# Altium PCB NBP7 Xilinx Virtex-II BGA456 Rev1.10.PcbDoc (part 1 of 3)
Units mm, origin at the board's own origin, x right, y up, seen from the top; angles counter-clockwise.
Board outline 69 x 80.99 mm, 6 copper layers (Top Layer, MidLayer1, InternalPlane1, InternalPlane2, MidLayer2, Bottom Layer); 101 components, 273 nets, 963 pads, 545 vias.
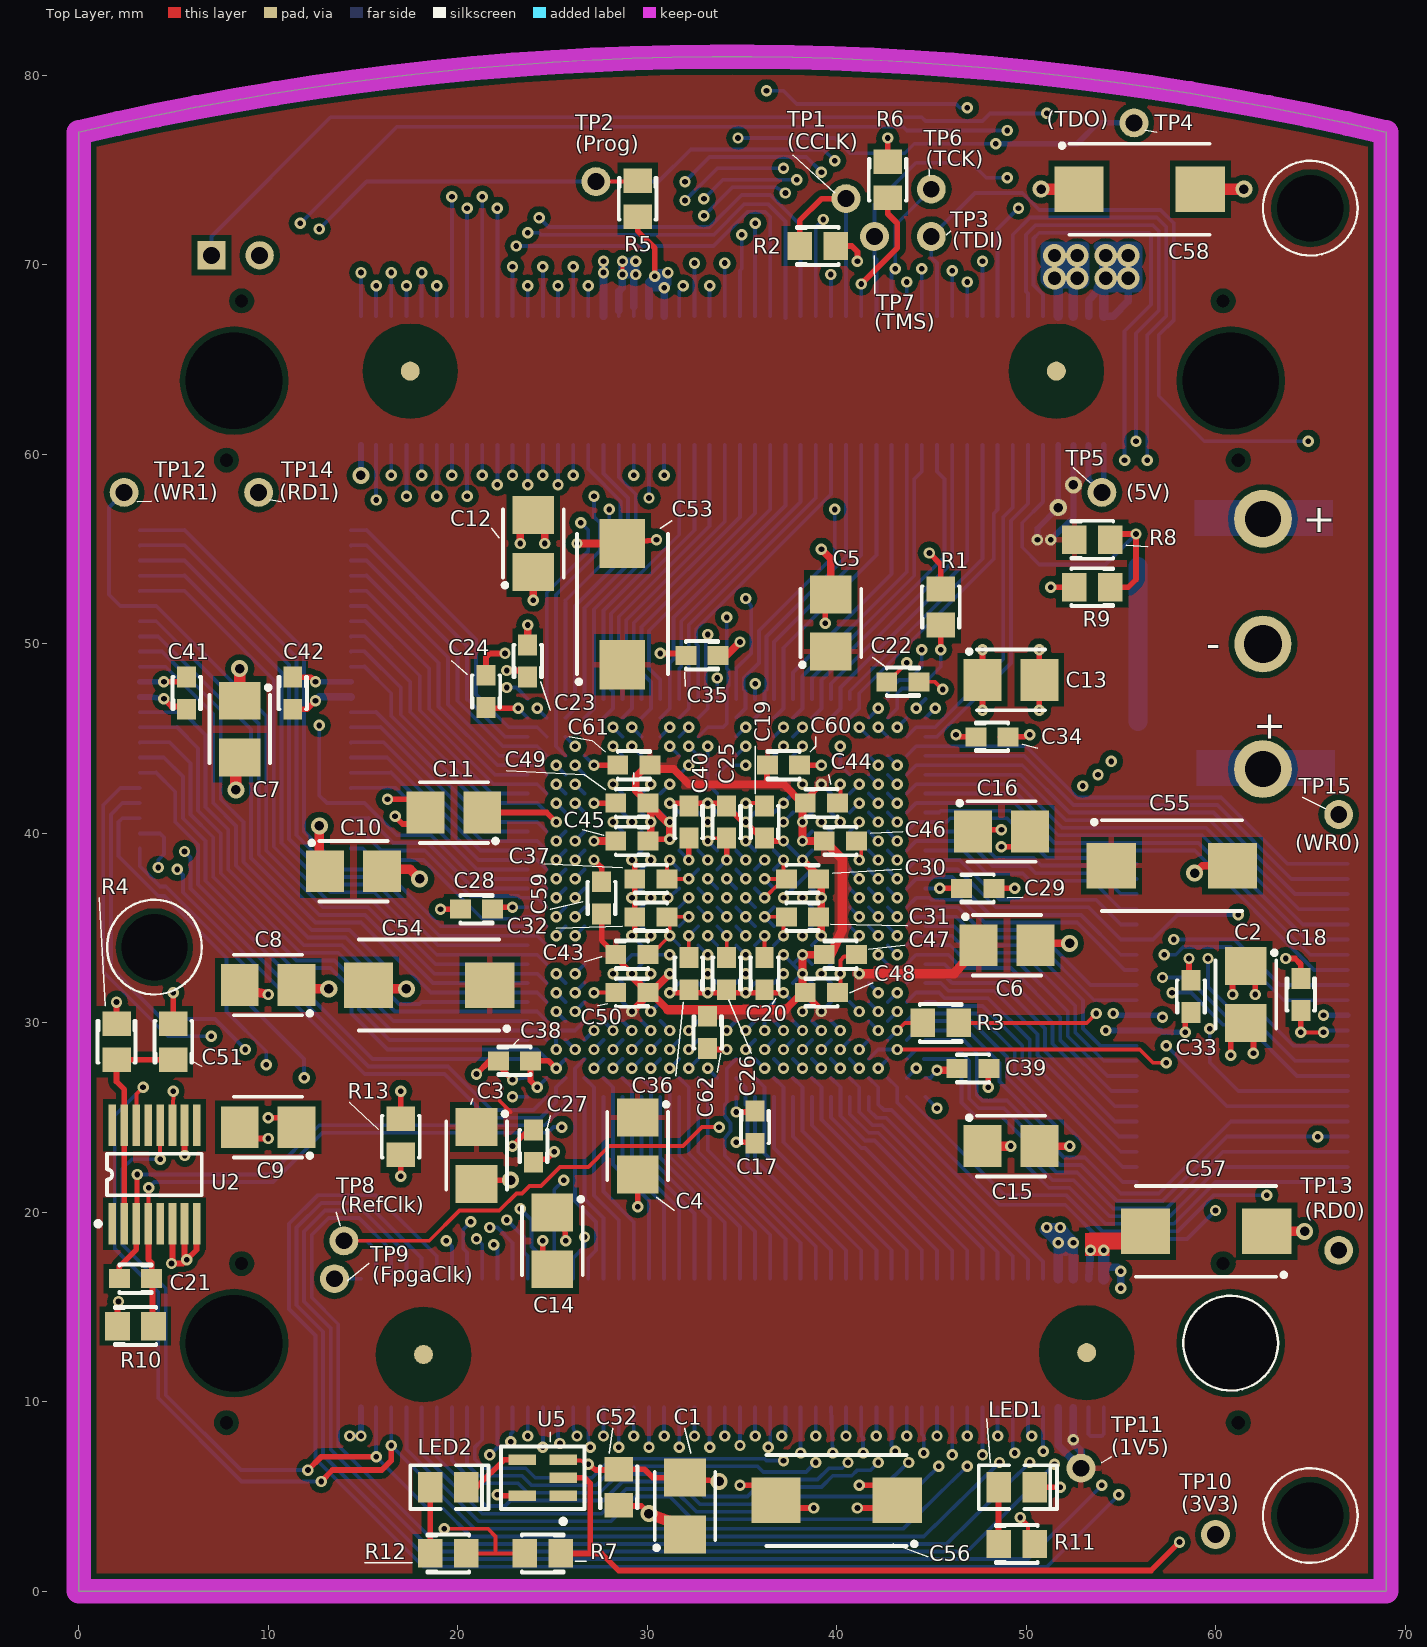
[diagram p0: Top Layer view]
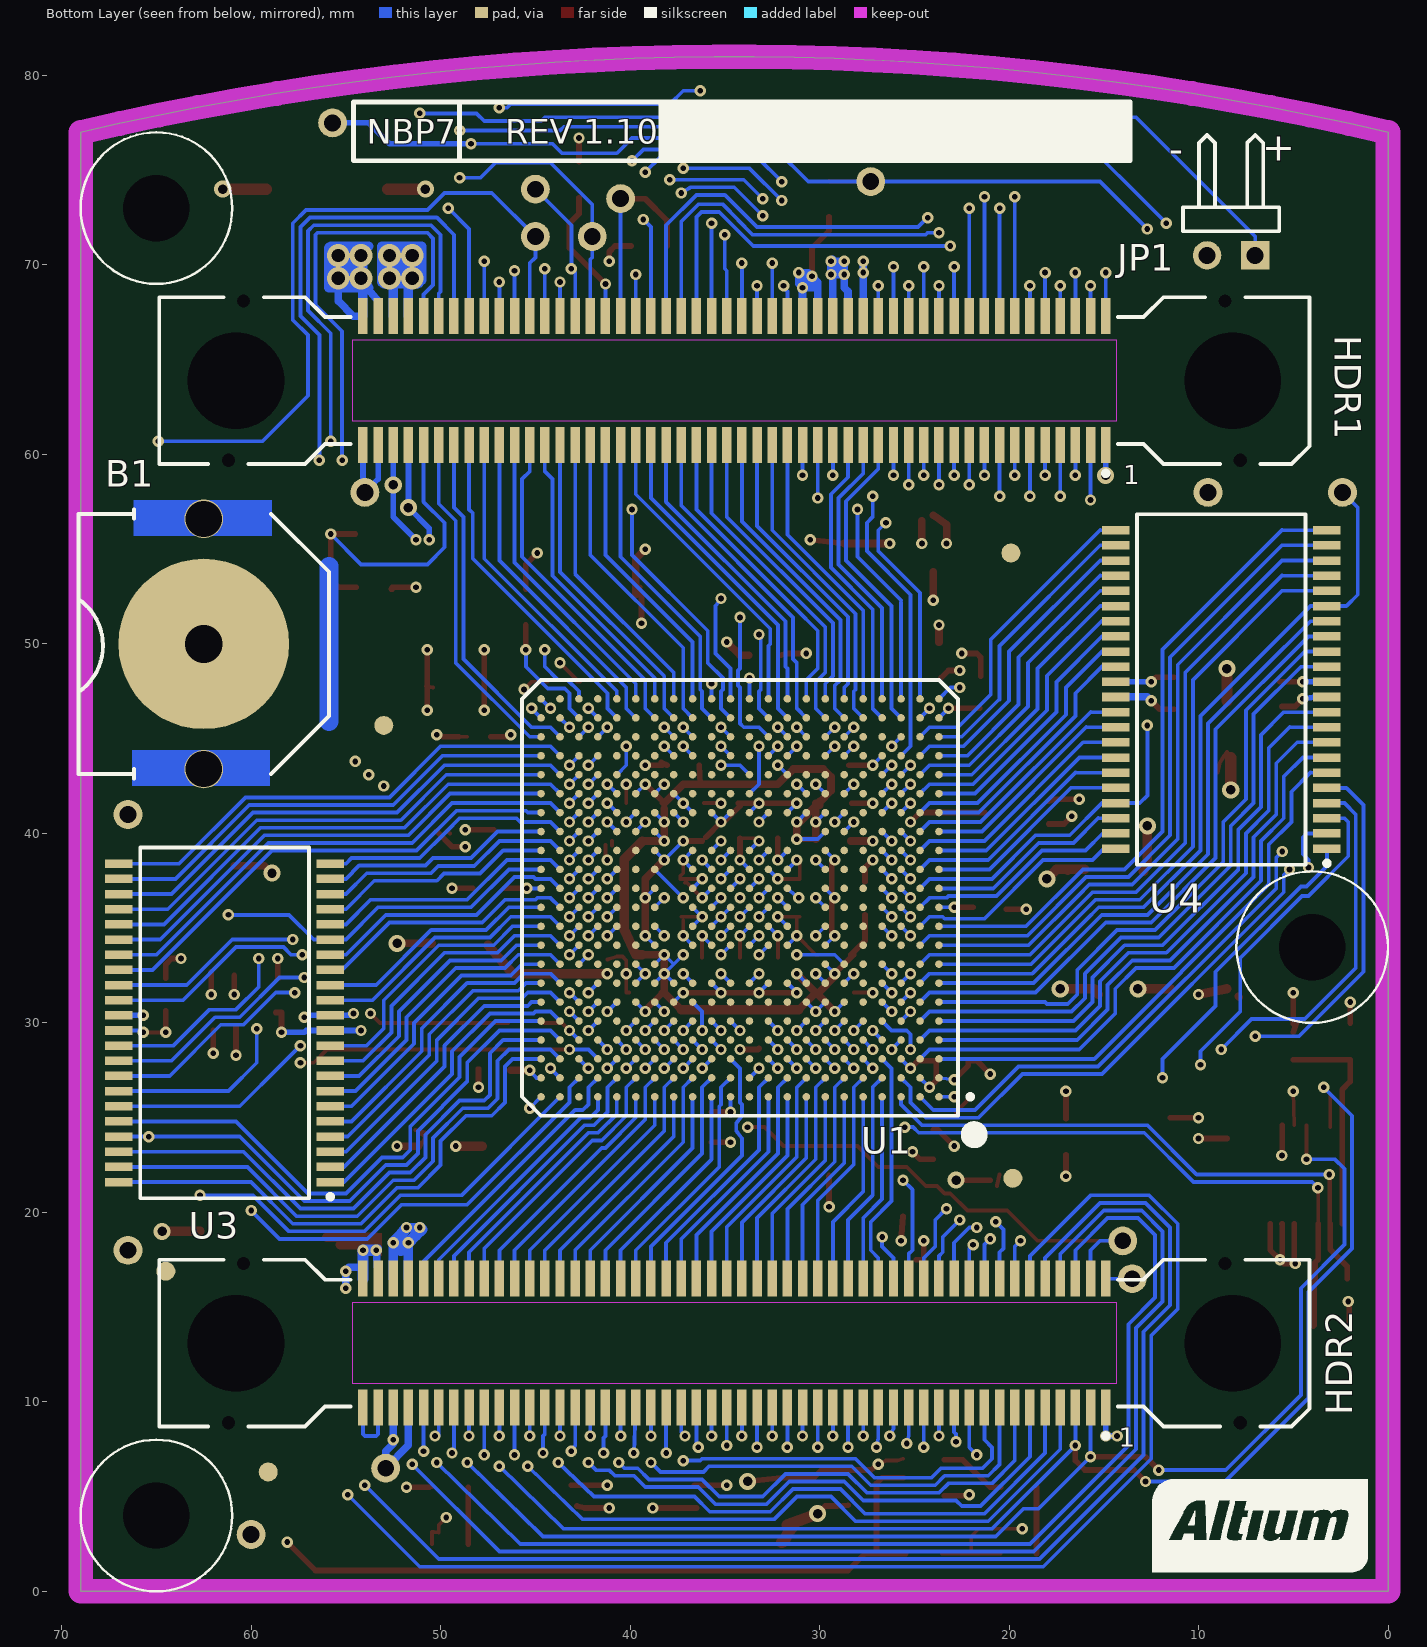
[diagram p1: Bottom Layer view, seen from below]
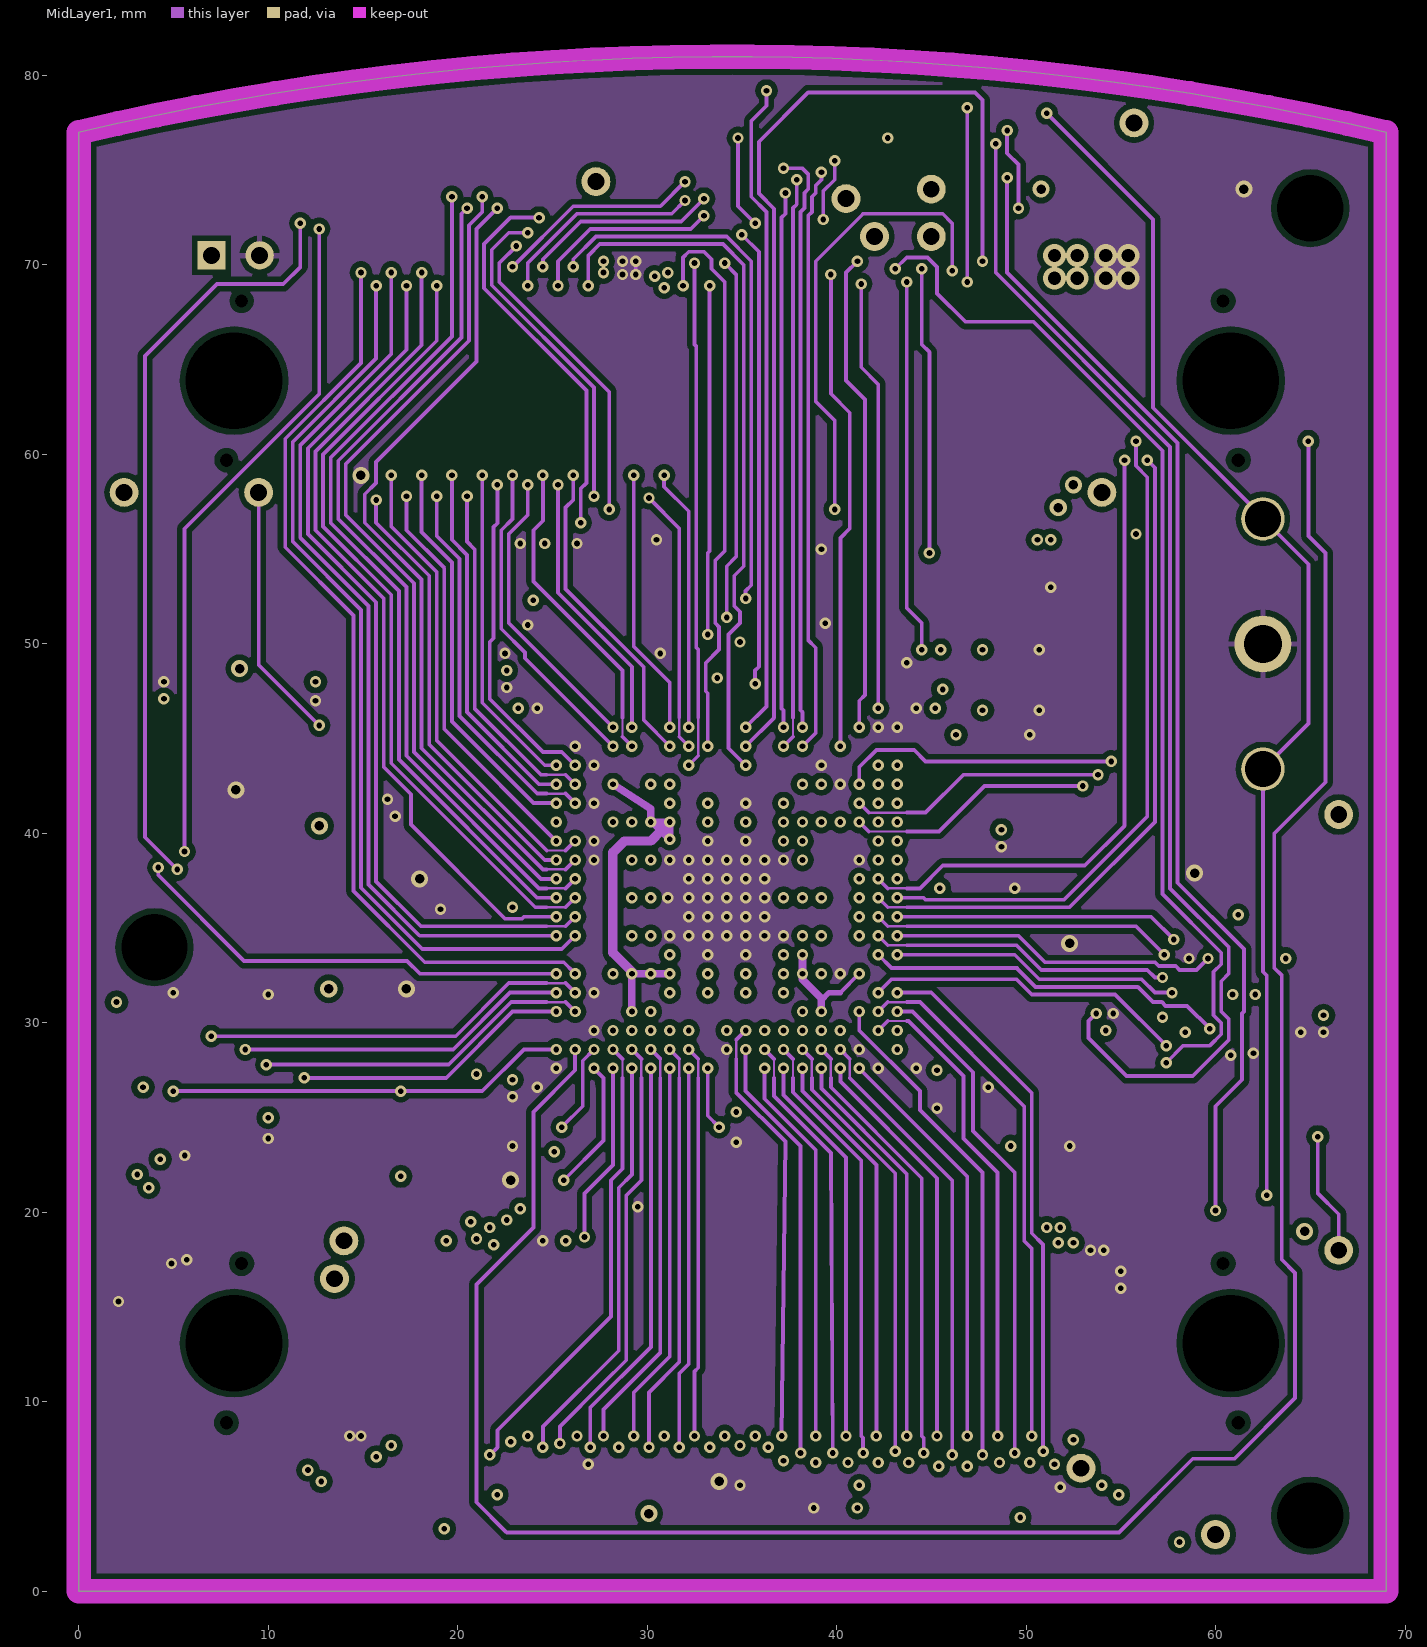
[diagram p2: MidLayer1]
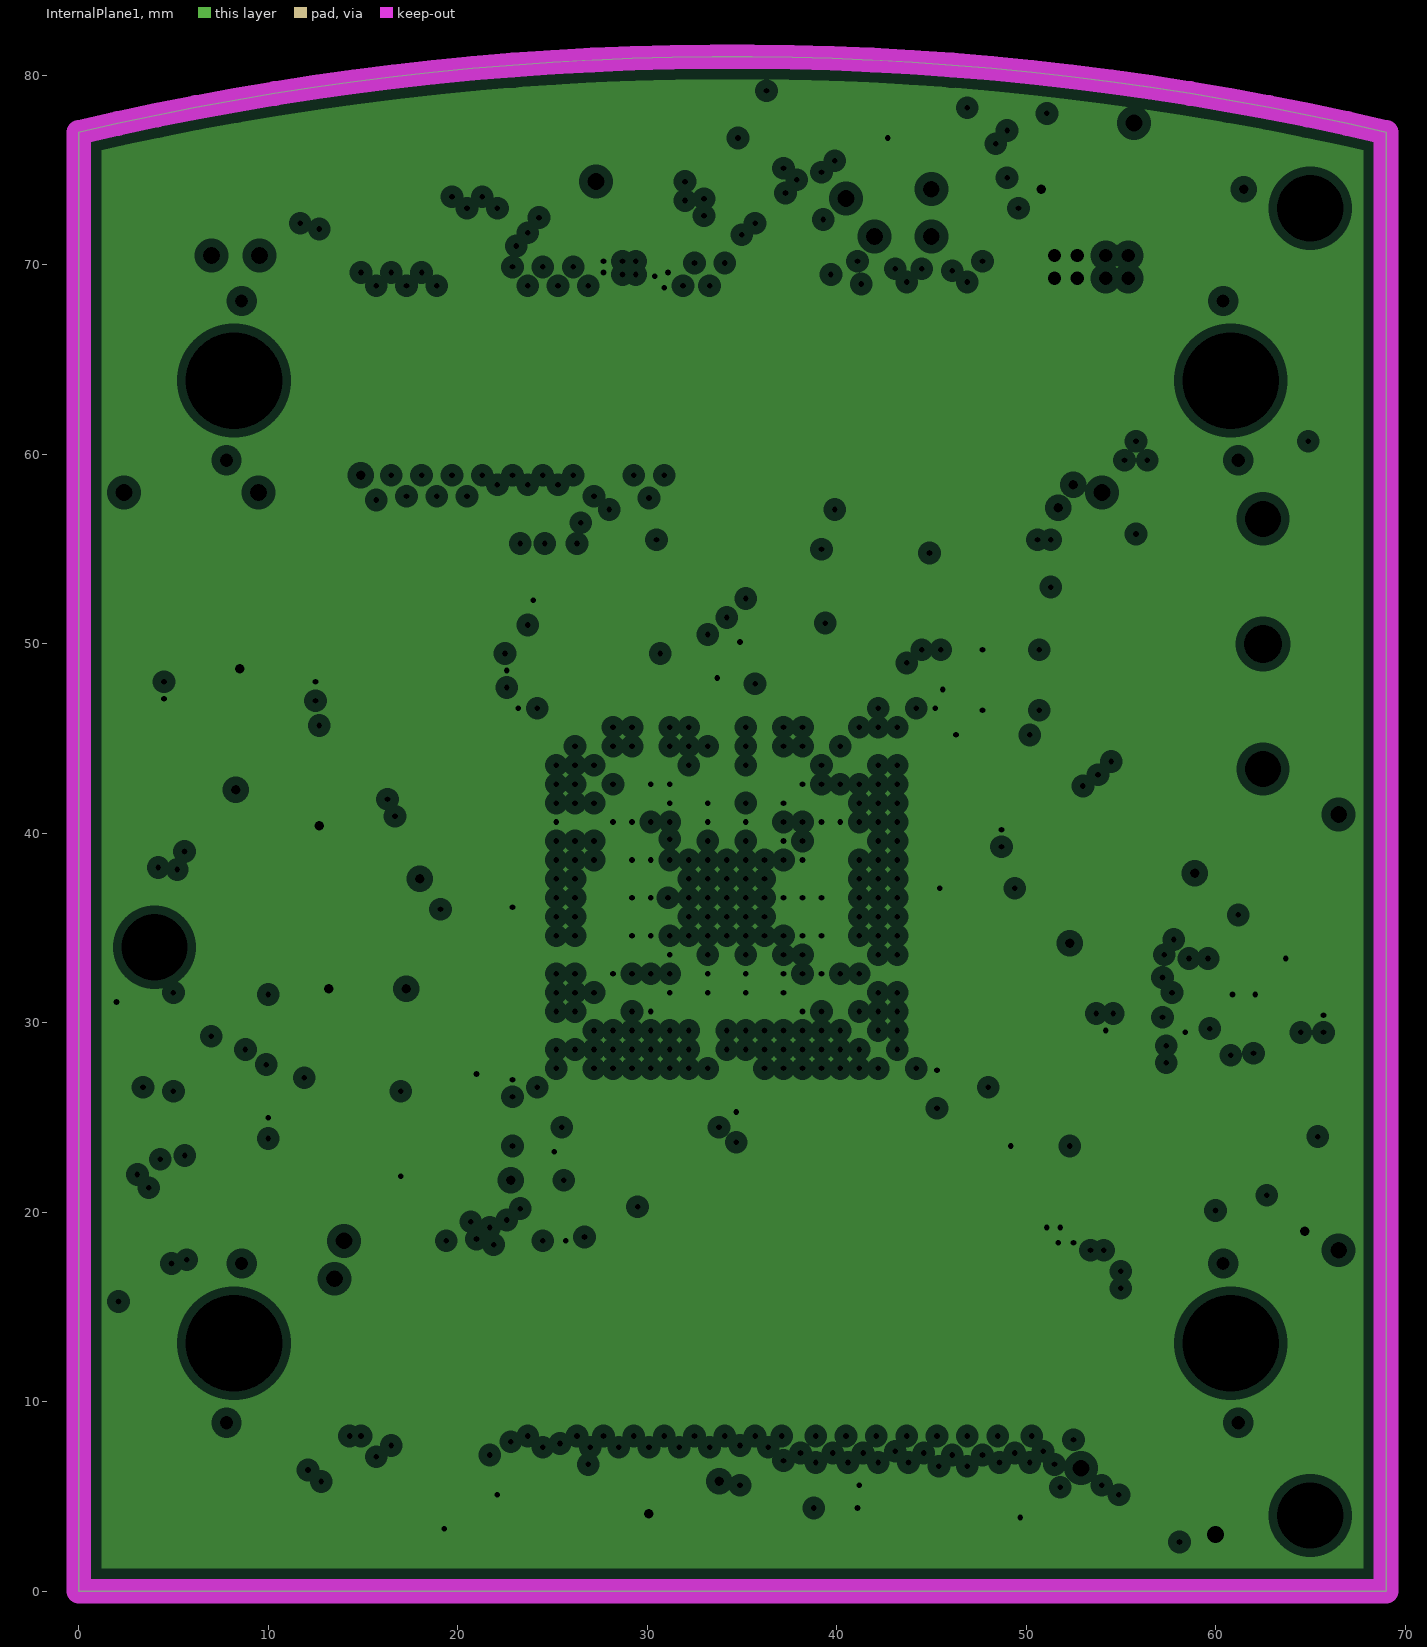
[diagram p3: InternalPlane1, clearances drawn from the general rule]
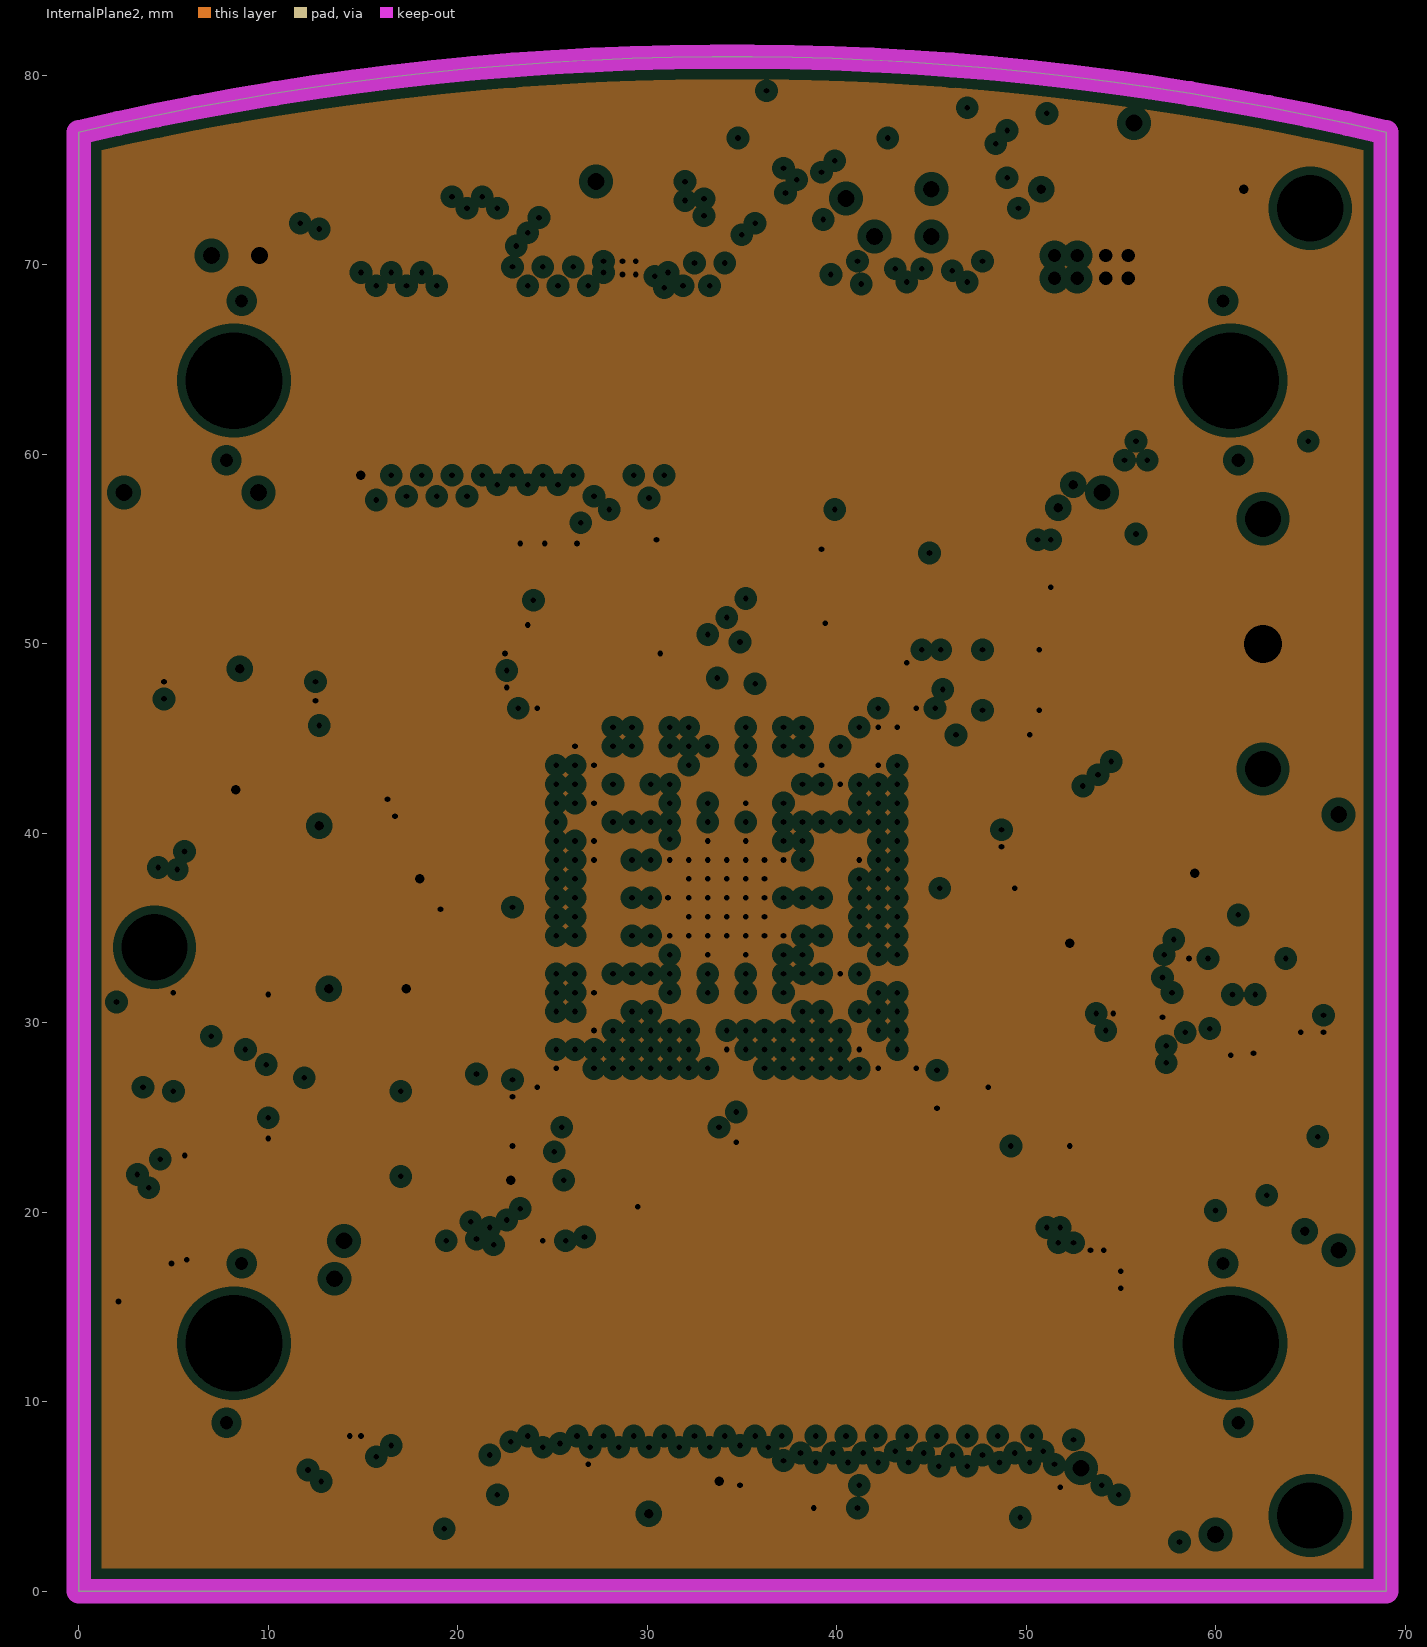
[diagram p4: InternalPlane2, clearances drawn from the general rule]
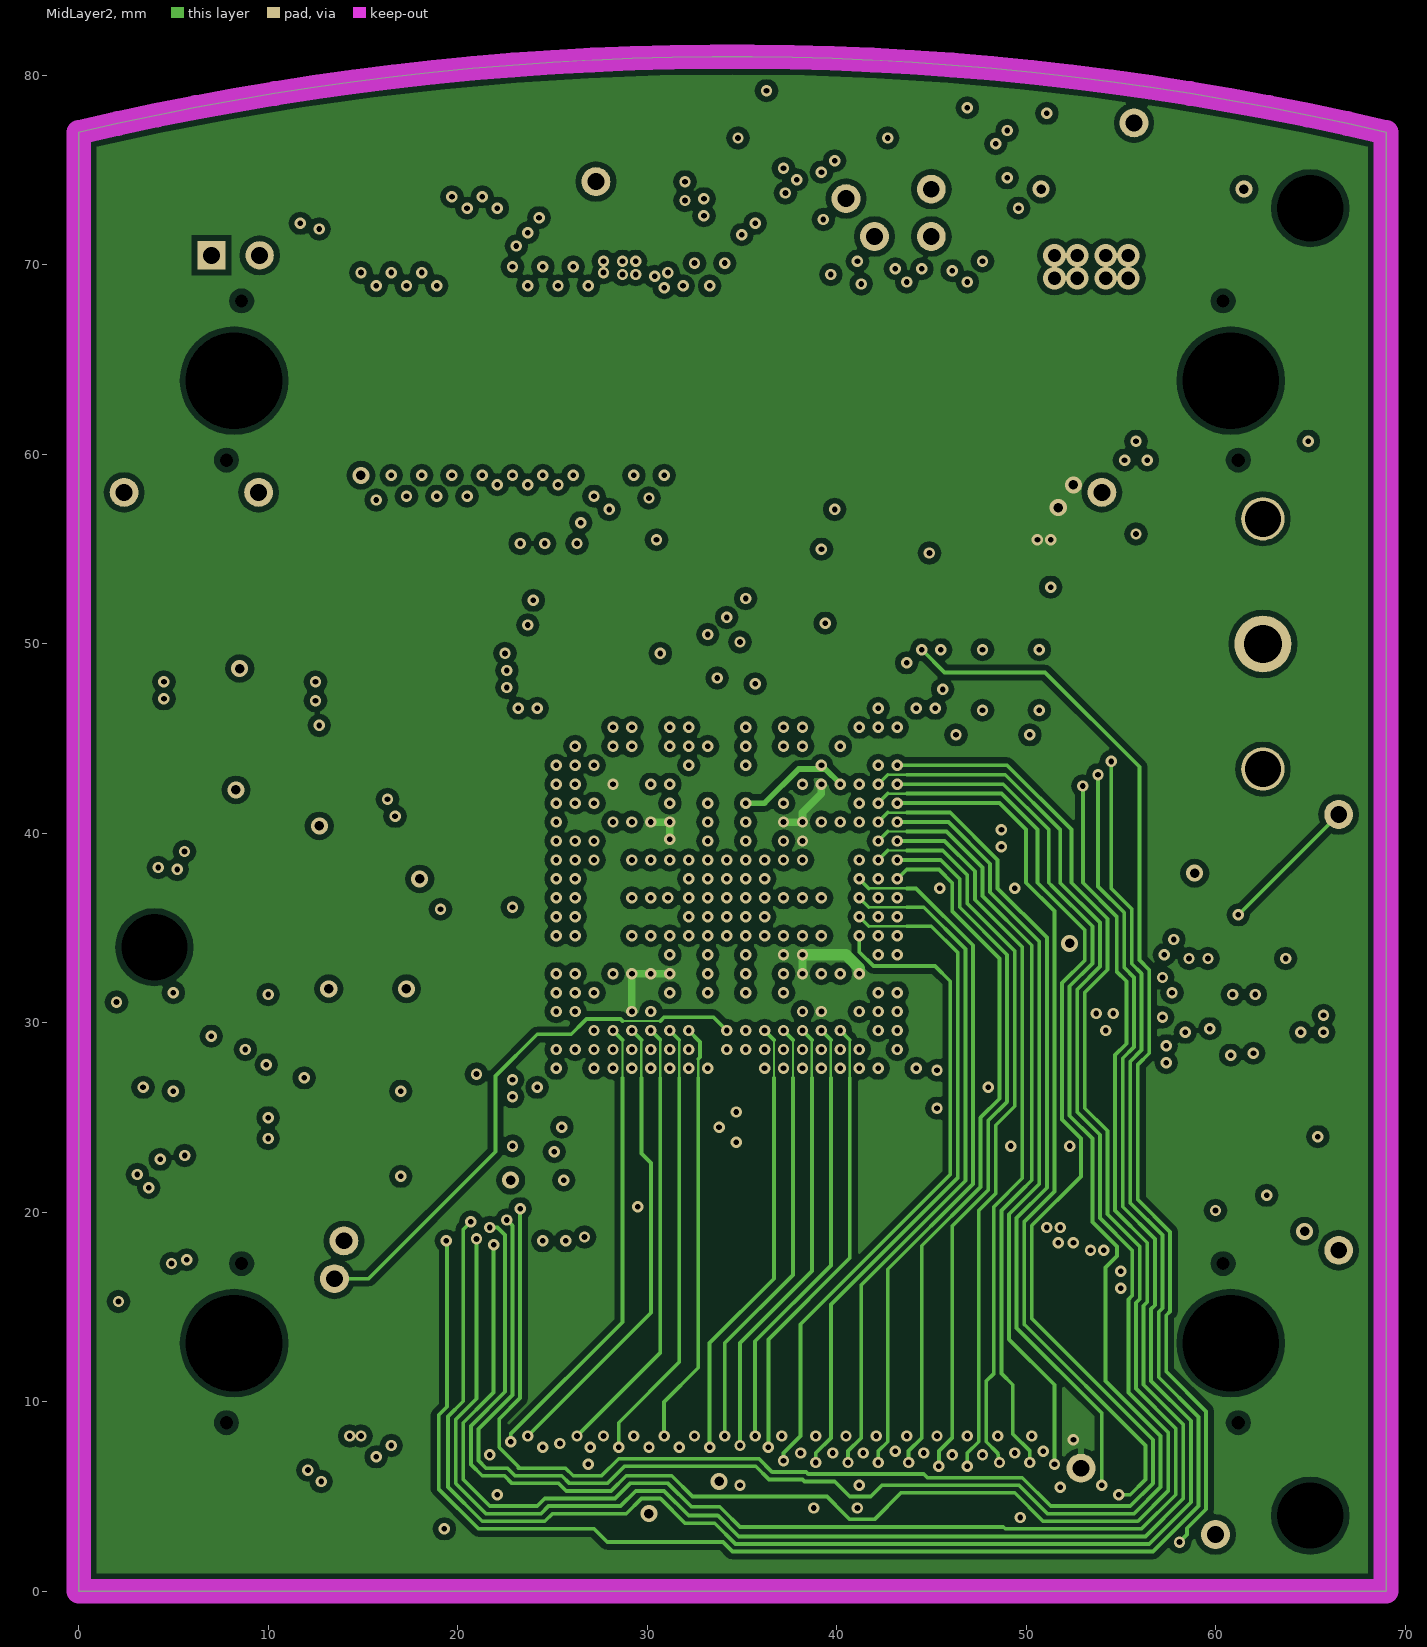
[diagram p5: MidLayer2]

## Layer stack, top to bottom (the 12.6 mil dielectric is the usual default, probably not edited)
Top Layer: signal copper 0.0356
Dielectric: core 0.32, FR-4, Dk 4.8
MidLayer1: signal copper 0.0356
Dielectric: prepreg 0.32, FR-4, Dk 4.8
InternalPlane1: plane copper 0.0356, net VCC
Dielectric: core 0.32, FR-4, Dk 4.8
InternalPlane2: plane copper 0.0356, net GND
Dielectric: prepreg 0.32, FR-4, Dk 4.8
MidLayer2: signal copper 0.0356
Dielectric: core 0.32, FR-4, Dk 4.8
Bottom Layer: signal copper 0.0356

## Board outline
0,0 0.001,77 cw(c34.5,-69.801) 69,77 69,0

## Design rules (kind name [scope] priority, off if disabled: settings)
Clearance "Fiducial Clearance" [InPadClass('Fiducials')] p1: gap=2
Clearance Clearance_Polygons [InPolygon] p2: gap=0.3
Clearance "Via Pad Same Net" [IsVia vs IsPad] p3: gap=0.2
Clearance "Via-Via Clearance" [IsVia vs IsVia] p4: gap=0.3
Clearance "Mid Layer Track - Via Clearance" [(OnMid  And IsTrack) vs IsVia] p5: gap=0.127
Clearance "Bottom Layer General Clearance" [All vs OnLayer('Bottom Layer')] p6: gap=0.2
Clearance "Top Layer General Clearance" [All vs OnLayer('Top Layer')] p7: gap=0.2
Clearance "Clearance Top Layer Pads" [(OnLayer('Top Layer')) vs (InPadClass('All Pads'))] p8: gap=0.254
Clearance "General Clearance" [All] p9: gap=0.2
ComponentClearance [All] p1: gap=0.2 collisioncheckmode=3 verticalgap=0.254 showdistances=FALSE
FabricationTestPointUsage TestPointUsage [All] p1 off: valid=0 allowmultiple=FALSE
FabricationTestpoint Testpoint [All] p1 off: side=3 testpointundercomponent=TRUE minsize=1.016 maxsize=2.54 preferedsize=1.524 minholesize=0 maxholesize=1.016 preferedholesize=0.813 testpointgrid=0.025 allowsidetop=TRUE allowsidebottom=TRUE usegrid=TRUE gridtolerance=0
HoleSize [All] p1: absolutevalues=TRUE maxlimit=10 minlimit=0.3 maxpercent=80.000 minpercent=20.000
PlaneClearance [All] p1: clearance=0.45
PlaneConnect [All] p1: planeconnectstyle=Direct reliefexpansion=0.5 reliefentries=4 reliefconductorwidth=0.25 reliefairgap=0.25
PolygonConnect [All] p1: connectstyle=Relief reliefconductorwidth=0.3 reliefentries=4 polygonreliefangle="90 Angle"
RoutingVias [All] p1: holewidth=0.3 width=0.6 viastyle="Through Hole" minholewidth=0.3 minwidth=0.5 maxholewidth=0.5 maxwidth=1
SMDNeckDown [All] p1: percent=100.000
SilkscreenOverComponentPads [All] p1: minsilkscreentomaskgap=0.254
SolderMaskExpansion SolderMaskExpansion_Vias [IsVia] p1: expansion=-0.65
SolderMaskExpansion [All] p2: expansion=0.25
Width [All] p1: maxlimit=1.5 minlimit=0.127 preferedwidth=0.2 toplayer_minwidth=0.2 toplayer_prefwidth=0.203 bottomlayer_minwidth=0.2
21 further rules are at their usual default settings.

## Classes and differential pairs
pad class Fiducials: Free-4 Free-5 Free-6 Free-7
pad class PAR_DATA: U1-AA3 U1-AA4 U1-AA18 U1-AB4 U1-R18 U1-V17 U1-W5 U1-W18 U1-Y4 U1-Y5
pad class IO_CLK: U1-AB12 U1-B11 U1-E12 U1-V11
pad class IO: U1-A4 U1-A5 U1-A6 U1-A10 U1-A13 U1-A17 U1-A18 U1-A19 U1-AA5 U1-AA10 U1-AA13 U1-AA17 U1-AA18 U1-AA20 U1-AB5 U1-AB10 U1-AB13 U1-AB17 U1-AB18 U1-B4 U1-B5 U1-B6 U1-B10 U1-B12 U1-B13 U1-B17 U1-B18 U1-B19 U1-C1 U1-C2 U1-C4 U1-C5 U1-C6 U1-C10 U1-C12 U1-C13 U1-C18 U1-C21 U1-D1 U1-D2 U1-D6 U1-D10 U1-D13 U1-D17 U1-D18 U1-D21 U1-E1 U1-E2 U1-E3 U1-E4 U1-E5 U1-E6 U1-E7 U1-E8 U1-E10 U1-E11 U1-E13 U1-E14 U1-E16 U1-E17 U1-E18 U1-E19 U1-E20 U1-E21 U1-E22 U1-F10 U1-F11 U1-F18 U1-G1 U1-G2 U1-G21 U1-G22 U1-H1 U1-H2 U1-H3 U1-H4 U1-H5 U1-H19 U1-H20 U1-H21 U1-H22 U1-J6 U1-J17 U1-J18 U1-K1 U1-K2 U1-K3 U1-K4 U1-K21 U1-K22 U1-L2 U1-L3 U1-L4 U1-L5 U1-L17 U1-L18 U1-L19 U1-L20 U1-L21 U1-L22 U1-M1 U1-M2 U1-M3 U1-M4 U1-M5 U1-M6 U1-M17 U1-M18 U1-M19 U1-M20 U1-M21 U1-N1 U1-N2 U1-N17 U1-N21 U1-P5 U1-P6 U1-P17 U1-R1 U1-R2 U1-R3 U1-R4 U1-R18 U1-R19 U1-R20 U1-R21 U1-R22 U1-T1 U1-T2 U1-T21 U1-T22 U1-U3 U1-U4 U1-U5 U1-U10 U1-U11 U1-U12 U1-U13 U1-V3 U1-V4 U1-V5 U1-V6 U1-V7 U1-V9 U1-V10 U1-V12 U1-V13 U1-V19 U1-V20 U1-V21 U1-V22 U1-W1 U1-W2 U1-W6 U1-W10 U1-W13 U1-W17 U1-W21 U1-W22
pad class IN_ONLY: U1-A11 U1-AA11 U1-AA12 U1-C11 U1-D12 U1-F11 U1-F12 U1-F14 U1-J22 U1-W11 U1-W12 U1-Y12
pad class 500andUp: U1-A8 U1-A9 U1-A14 U1-A15 U1-AA8 U1-AA9 U1-AA14 U1-AA15 U1-AB8 U1-AB14 U1-AB15 U1-B8 U1-B9 U1-B14 U1-B15 U1-C9 U1-C14 U1-C15 U1-D9 U1-D14 U1-D15 U1-E9 U1-F9 U1-J1 U1-J2 U1-J3 U1-J4 U1-J5 U1-J19 U1-J20 U1-J21 U1-J22 U1-K5 U1-K6 U1-K17 U1-K18 U1-K19 U1-K20 U1-L6 U1-N3 U1-N4 U1-N5 U1-N6 U1-N18 U1-N19 U1-N20 U1-P1 U1-P2 U1-P3 U1-P4 U1-P18 U1-P19 U1-P20 U1-P21 U1-P22 U1-U11 U1-U14 U1-V9 U1-V14 U1-W8 U1-W9 U1-W14 U1-Y8 U1-Y14

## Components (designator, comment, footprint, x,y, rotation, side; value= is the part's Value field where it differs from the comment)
B1 "CoinCellHolder" COINCELLHOLDER12THM 62.5,43.396 r90 bottom
C1 "10uF" MCCT-B 32,4.5 r90 top
C2 "10uF" MCCT-B 61.6,31.5 r270 top
C3 "10uF" MCCT-B 21,23 r270 top
C4 "10uF" MCCT-B 29.5,23.5 r270 top
C5 "10uF" MCCT-B 39.7,51.1 r90 top
C6 "10uF" MCCT-B 49,34.1 r0 top
C7 "10uF" MCCT-B 8.5,45.5 r270 top
C8 "10uF" MCCT-B 10,32 r180 top
C9 "10uF" MCCT-B 10,24.5 r180 top
C10 "10uF" MCCT-B 14.5,38 r0 top
C11 "10uF" MCCT-B 19.8,41.1 r180 top
C12 "10uF" MCCT-B 24,55.3 r90 top
C13 "10uF" MCCT-B 49.2,48.1 r0 top
C14 "10uF" MCCT-B 25,18.5 r270 top
C15 "10uF" MCCT-B 49.2,23.5 r0 top
C16 "10uF" MCCT-B 48.7,40.1 r0 top
C17 "10nF" CC1608-0603#1 35.7,24.5 r270 top
C18 "10nF" CC1608-0603#1 64.5,31.5 r270 top
C19 "10nF" CC1608-0603#1 36.2,40.6 r90 top
C20 "10nF" CC1608-0603#2 36.2,32.6 r90 top
C21 "10nF" CC1608-0603#1 3,16.5 r180 top
C22 "10nF" CC1608-0603#1 43.5,48 r180 top
C23 "10nF" CC1608-0603#1 23.7,49.1 r90 top
C24 "10nF" CC1608-0603#1 21.5,47.5 r90 top
C25 "10nF" CC1608-0603#1 34.2,40.6 r270 top
C26 "10nF" CC1608-0603#1 34.2,32.6 r90 top
C27 "10nF" CC1608-0603#1 24,23.5 r90 top
C28 "10nF" CC1608-0603#1 21,36 r180 top
C29 "10nF" CC1608-0603#1 47.45,37.1 r0 top
C30 "10nF" CC1608-0603#1 38.2,37.6 r180 top
C31 "10nF" CC1608-0603#1 38.2,35.6 r180 top
C32 "10nF" CC1608-0603#1 30.2,35.6 r0 top
C33 "10nF" CC1608-0603#1 58.7,31.4 r90 top
C34 "10nF" CC1608-0603#1 48.2,45.1 r0 top
C35 "10nF" CC1608-0603#1 32.9,49.4 r180 top
C36 "10nF" CC1608-0603#1 32.2,32.6 r90 top
C37 "10nF" CC1608-0603#1 30.2,37.6 r0 top
C38 "10nF" CC1608-0603#1 23,28 r0 top
C39 "10nF" CC1608-0603#1 47.2,27.6 r0 top
C40 "10nF" CC1608-0603#1 32.2,40.6 r270 top
C41 "10nF" CC1608-0603#1 5.7,47.4 r90 top
C42 "10nF" CC1608-0603#1 11.3,47.4 r270 top
C43 "10nF" CC1608-0603#1 29.2,33.6 r0 top
C44 "10nF" CC1608-0603#1 39.2,41.6 r0 top
C45 "10nF" CC1608-0603#1 29.2,39.6 r180 top
C46 "10nF" CC1608-0603#1 40.2,39.6 r0 top
C47 "10nF" CC1608-0603#1 40.2,33.6 r0 top
C48 "10nF" CC1608-0603#1 39.2,31.6 r0 top
C49 "10nF" CC1608-0603#1 29.2,41.6 r180 top
C50 "10nF" CC1608-0603#1 29.2,31.6 r180 top
C51 "0.1uF" CC2012-0805 5,29 r90 top
C52 "0.1uF" CC2012-0805 28.5,5.5 r90 top
C53 "220uF/4V" MCCT-D 28.7,52.1 r90 top
C54 "220uF/4V" MCCT-D 18.5,32 r180 top
C55 "220uF/4V" MCCT-D 57.7,38.3 r0 top
C56 "220uF/4V" MCCT-D 40,4.8 r180 top
C57 "220uF/4V" MCCT-D 59.5,19 r180 top
C58 "220uF/4V" MCCT-D 56,74 r0 top
C59 "10nF" CC1608-0603#1 27.6,36.6 r90 top
C60 "10nF" CC1608-0603#1 37.2,43.6 r0 top
C61 "10nF" CC1608-0603#1 29.3,43.6 r180 top
C62 "10nF" CC1608-0603#1 33.2,29.5 r270 top
HDR1 "54075-1009-HD1" 54075 34.5,63.9 r0 bottom locked
HDR2 "54075-1009-HD2" 54075 34.5,13.1 r0 bottom locked
JP1 "Header 2H" HDR1X2H 7,70.5 r0 bottom
LED1 "HSMH-C170" "SMD _LED" 49.5,5.5 r180 top locked
LED2 "HSMG-C170" "SMD _LED" 19.5,5.5 r180 top locked
R1 "100R" CC2012-0805 45.5,51.95 r90 top
R2 "100R" CC2012-0805 39,71 r0 top
R3 "100R" CC2012-0805 45.5,30 r180 top
R4 "100R" CC2012-0805 2,29 r270 top
R5 "470R" CC2012-0805 29.5,73.5 r270 top
R6 "470R" CC2012-0805 42.7,74.5 r270 top
R7 "470R" CC2012-0805 24.5,2 r180 top
R8 "DO NOT INSTALL" CC2012-0805 53.5,55.5 r0 top
R9 "47R" CC2012-0805 53.5,53 r180 top
R10 "1M" CC2012-0805 3,14 r0 top
R11 "270R" CC2012-0805 49.5,2.5 r0 top
R12 "270R" CC2012-0805 19.5,2 r0 top
R13 "4k7" CR2012-0805 17,24 r90 top
TP1 "(CCLK)" TestPin 40.5,73.5 r0 top
TP2 "(Prog)" TestPin 27.3,74.4 r90 top
TP3 "(TDI)" TestPin 45,71.5 r90 top
TP4 "(TDO)" TestPin 55.7,77.5 r90 top
TP5 "(5V)" TestPin 54,58 r90 top
TP6 "(TCK)" TestPin 45,74 r90 top
TP7 "(TMS)" TestPin 42,71.5 r90 top
TP8 "(RefClk)" TestPin 14,18.5 r90 top
TP9 "(FpgaClk)" TestPin 13.5,16.5 r90 top
TP10 "(3V3)" TestPin 60,3 r90 top
TP11 "(1V5)" TestPin 52.9,6.5 r90 top
TP12 "(WR1)" TestPin 2.4,58 r90 top
TP13 "(RD0)" TestPin 66.5,18 r90 top
TP14 "(RD1)" TestPin 9.5,58 r90 top
TP15 "(WR0)" TestPin 66.5,41 r90 top
U1 "XC2V1000-4FG456C" FG456 34.2,36.6 r0 bottom
U2 "MAX1617DBR2" QSOP16 4,22 r0 top
U3 "SRAM 512Kx16 TSOP44" SO-G44/P.8 61.4,30 r90 bottom
U4 "SRAM 512Kx16 TSOP44" SO-G44/P.8 8.8,47.6 r90 bottom
U5 "SN74LVC1G04DBV" SO-G5/P.95 24.5,6 r90 top

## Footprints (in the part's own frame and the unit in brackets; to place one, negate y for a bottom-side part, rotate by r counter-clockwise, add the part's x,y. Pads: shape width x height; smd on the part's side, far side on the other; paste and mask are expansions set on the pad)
54075 [mm] "Connector; Docking Station, Receptacle; 100 Position; Vertical"
  rect 0.5x1.9 smd: 1(-19.6,3.4) 2(-19.6,-3.4) 3(-18.8,3.4) 4(-18.8,-3.4) 5(-18,3.4) 6(-18,-3.4) 7(-17.2,3.4) 8(-17.2,-3.4) 9(-16.4,3.4) 10(-16.4,-3.4) 11(-15.6,3.4) 12(-15.6,-3.4) 13(-14.8,3.4) 14(-14.8,-3.4) 15(-14,3.4) 16(-14,-3.4) 17(-13.2,3.4) 18(-13.2,-3.4) 19(-12.4,3.4) 20(-12.4,-3.4) 21(-11.6,3.4) 22(-11.6,-3.4) 23(-10.8,3.4) 24(-10.8,-3.4) 25(-10,3.4) 26(-10,-3.4) 27(-9.2,3.4) 28(-9.2,-3.4) 29(-8.4,3.4) 30(-8.4,-3.4) 31(-7.6,3.4) 32(-7.6,-3.4) 33(-6.8,3.4) 34(-6.8,-3.4) 35(-6,3.4) 36(-6,-3.4) 37(-5.2,3.4) 38(-5.2,-3.4) 39(-4.4,3.4) 40(-4.4,-3.4) 41(-3.6,3.4) 42(-3.6,-3.4) 43(-2.8,3.4) 44(-2.8,-3.4) 45(-2,3.4) 46(-2,-3.4) 47(-1.2,3.4) 48(-1.2,-3.4) 49(-0.4,3.4) 50(-0.4,-3.4) 51(0.4,3.4) 52(0.4,-3.4) 53(1.2,3.4) 54(1.2,-3.4) 55(2,3.4) 56(2,-3.4) 57(2.8,3.4) 58(2.8,-3.4) 59(3.6,3.4) 60(3.6,-3.4) 61(4.4,3.4) 62(4.4,-3.4) 63(5.2,3.4) 64(5.2,-3.4) 65(6,3.4) 66(6,-3.4) 67(6.8,3.4) 68(6.8,-3.4) 69(7.6,3.4) 70(7.6,-3.4) 71(8.4,3.4) 72(8.4,-3.4) 73(9.2,3.4) 74(9.2,-3.4) 75(10,3.4) 76(10,-3.4) 77(10.8,3.4) 78(10.8,-3.4) 79(11.6,3.4) 80(11.6,-3.4) 81(12.4,3.4) 82(12.4,-3.4) 83(13.2,3.4) 84(13.2,-3.4) 85(14,3.4) 86(14,-3.4) 87(14.8,3.4) 88(14.8,-3.4) 89(15.6,3.4) 90(15.6,-3.4) 91(16.4,3.4) 92(16.4,-3.4) 93(17.2,3.4) 94(17.2,-3.4) 95(18,3.4) 96(18,-3.4) 97(18.8,3.4) 98(18.8,-3.4) 99(19.6,3.4) 100(19.6,-3.4)
  round 0.5 hole 0.7 unplated: MH1(-26.7,4.2) MH2(-25.9,-4.2) MH3(26.7,4.2) MH4(25.9,-4.2)
  round 4.8 hole 5.1 unplated: MH5(-26.3,0) MH6(26.3,0)
  Top Layer keep-out region: -20.15,2.15 20.15,2.15 20.15,-2.15 -20.15,-2.15
  silkscreen extent -30.35,-4.4 30.35,5.02
CC1608-0603#1 [mm]
  rect 1.1x1 smd: 1(-0.85,0) 2(0.85,0)
  silkscreen extent -0.85,-0.75 0.85,0.75
CC1608-0603#2 [mm]
  rect 1.1x0.95 smd: 1(-0.85,0) 2(0.85,0)
  silkscreen extent -0.85,-0.75 0.85,0.75
CC2012-0805 [mm]
  rect 1.3x1.5 smd: 1(-0.95,0) 2(0.95,0)
  silkscreen extent -1.1,-1 1.1,1
COINCELLHOLDER12THM [mil] "Coin Cell Holder For 12\" Coin Battery Cell"
  round 80 / inner round 90 / far side round 120 hole 75: 0(0,0) 1(520,0)
  round 354.33 / inner round 118.11 / far side round 118.11 hole 78.74: 2(260,0)
  silkscreen extent -20,-260 540,261
CR2012-0805 [mm]
  rect 1.3x1.5 smd: 1(-0.95,0) 2(0.95,0)
  silkscreen extent -1.1,-1 1.1,1
FG456 [mm] "456-Ball Fine Pitch Ball Grid Array (FG456)"
  round 0.4 smd mask+0.2: A1(-10.5,10.5) A2(-9.5,10.5) A3(-8.5,10.5) A4(-7.5,10.5) A5(-6.5,10.5) A6(-5.5,10.5) A7(-4.5,10.5) A8(-3.5,10.5) A9(-2.5,10.5) A10(-1.5,10.5) A11(-0.5,10.5) A12(0.5,10.5) A13(1.5,10.5) A14(2.5,10.5) A15(3.5,10.5) A16(4.5,10.5) A17(5.5,10.5) A18(6.5,10.5) A19(7.5,10.5) A20(8.5,10.5) A21(9.5,10.5) A22(10.5,10.5) AA1(-10.5,-9.5) AA2(-9.5,-9.5) AA3(-8.5,-9.5) AA4(-7.5,-9.5) AA5(-6.5,-9.5) AA6(-5.5,-9.5) AA7(-4.5,-9.5) AA8(-3.5,-9.5) AA9(-2.5,-9.5) AA10(-1.5,-9.5) AA11(-0.5,-9.5) AA12(0.5,-9.5) AA13(1.5,-9.5) AA14(2.5,-9.5) AA15(3.5,-9.5) AA16(4.5,-9.5) AA17(5.5,-9.5) AA18(6.5,-9.5) AA19(7.5,-9.5) AA20(8.5,-9.5) AA21(9.5,-9.5) AA22(10.5,-9.5) AB1(-10.5,-10.5) AB2(-9.5,-10.5) AB3(-8.5,-10.5) AB4(-7.5,-10.5) AB5(-6.5,-10.5) AB6(-5.5,-10.5) AB7(-4.5,-10.5) AB8(-3.5,-10.5) AB9(-2.5,-10.5) AB10(-1.5,-10.5) AB11(-0.5,-10.5) AB12(0.5,-10.5) AB13(1.5,-10.5) AB14(2.5,-10.5) AB15(3.5,-10.5) AB16(4.5,-10.5) AB17(5.5,-10.5) AB18(6.5,-10.5) AB19(7.5,-10.5) AB20(8.5,-10.5) AB21(9.5,-10.5) AB22(10.5,-10.5) B1(-10.5,9.5) B2(-9.5,9.5) B3(-8.5,9.5) B4(-7.5,9.5) B5(-6.5,9.5) B6(-5.5,9.5) B7(-4.5,9.5) B8(-3.5,9.5) B9(-2.5,9.5) B10(-1.5,9.5) B11(-0.5,9.5) B12(0.5,9.5) B13(1.5,9.5) B14(2.5,9.5) B15(3.5,9.5) B16(4.5,9.5) B17(5.5,9.5) B18(6.5,9.5) B19(7.5,9.5) B20(8.5,9.5) B21(9.5,9.5) B22(10.5,9.5) C1(-10.5,8.5) C2(-9.5,8.5) C3(-8.5,8.5) C4(-7.5,8.5) C5(-6.5,8.5) C6(-5.5,8.5) C7(-4.5,8.5) C8(-3.5,8.5) C9(-2.5,8.5) C10(-1.5,8.5) C11(-0.5,8.5) C12(0.5,8.5) C13(1.5,8.5) C14(2.5,8.5) C15(3.5,8.5) C16(4.5,8.5) C17(5.5,8.5) C18(6.5,8.5) C19(7.5,8.5) C20(8.5,8.5) C21(9.5,8.5) C22(10.5,8.5) D1(-10.5,7.5) D2(-9.5,7.5) D3(-8.5,7.5) D4(-7.5,7.5) D5(-6.5,7.5) D6(-5.5,7.5) D7(-4.5,7.5) D8(-3.5,7.5) D9(-2.5,7.5) D10(-1.5,7.5) D11(-0.5,7.5) D12(0.5,7.5) D13(1.5,7.5) D14(2.5,7.5) D15(3.5,7.5) D16(4.5,7.5) D17(5.5,7.5) D18(6.5,7.5) D19(7.5,7.5) D20(8.5,7.5) D21(9.5,7.5) D22(10.5,7.5) E1(-10.5,6.5) E2(-9.5,6.5) E3(-8.5,6.5) E4(-7.5,6.5) E5(-6.5,6.5) E6(-5.5,6.5) E7(-4.5,6.5) E8(-3.5,6.5) E9(-2.5,6.5) E10(-1.5,6.5) E11(-0.5,6.5) E12(0.5,6.5) E13(1.5,6.5) E14(2.5,6.5) E15(3.5,6.5) E16(4.5,6.5) E17(5.5,6.5) E18(6.5,6.5) E19(7.5,6.5) E20(8.5,6.5) E21(9.5,6.5) E22(10.5,6.5) F1(-10.5,5.5) F2(-9.5,5.5) F3(-8.5,5.5) F4(-7.5,5.5) F5(-6.5,5.5) F6(-5.5,5.5) F7(-4.5,5.5) F8(-3.5,5.5) F9(-2.5,5.5) F10(-1.5,5.5) F11(-0.5,5.5) F12(0.5,5.5) F13(1.5,5.5) F14(2.5,5.5) F15(3.5,5.5) F16(4.5,5.5) F17(5.5,5.5) F18(6.5,5.5) F19(7.5,5.5) F20(8.5,5.5) F21(9.5,5.5) F22(10.5,5.5) G1(-10.5,4.5) G2(-9.5,4.5) G3(-8.5,4.5) G4(-7.5,4.5) G5(-6.5,4.5) G6(-5.5,4.5) G7(-4.5,4.5) G8(-3.5,4.5) G9(-2.5,4.5) G10(-1.5,4.5) G11(-0.5,4.5) G12(0.5,4.5) G13(1.5,4.5) G14(2.5,4.5) G15(3.5,4.5) G16(4.5,4.5) G17(5.5,4.5) G18(6.5,4.5) G19(7.5,4.5) G20(8.5,4.5) G21(9.5,4.5) G22(10.5,4.5) H1(-10.5,3.5) H2(-9.5,3.5) H3(-8.5,3.5) H4(-7.5,3.5) H5(-6.5,3.5) H6(-5.5,3.5) H7(-4.5,3.5) H16(4.5,3.5) H17(5.5,3.5) H18(6.5,3.5) H19(7.5,3.5) H20(8.5,3.5) H21(9.5,3.5) H22(10.5,3.5) J1(-10.5,2.5) J2(-9.5,2.5) J3(-8.5,2.5) J4(-7.5,2.5) J5(-6.5,2.5) J6(-5.5,2.5) J7(-4.5,2.5) J9(-2.5,2.5) J10(-1.5,2.5) J11(-0.5,2.5) J12(0.5,2.5) J13(1.5,2.5) J14(2.5,2.5) J16(4.5,2.5) J17(5.5,2.5) J18(6.5,2.5) J19(7.5,2.5) J20(8.5,2.5) J21(9.5,2.5) J22(10.5,2.5) K1(-10.5,1.5) K2(-9.5,1.5) K3(-8.5,1.5) K4(-7.5,1.5) K5(-6.5,1.5) K6(-5.5,1.5) K7(-4.5,1.5) K9(-2.5,1.5) K10(-1.5,1.5) K11(-0.5,1.5) K12(0.5,1.5) K13(1.5,1.5) K14(2.5,1.5) K16(4.5,1.5) K17(5.5,1.5) K18(6.5,1.5) K19(7.5,1.5) K20(8.5,1.5) K21(9.5,1.5) K22(10.5,1.5) L1(-10.5,0.5) L2(-9.5,0.5) L3(-8.5,0.5) L4(-7.5,0.5) L5(-6.5,0.5) L6(-5.5,0.5) L7(-4.5,0.5) L9(-2.5,0.5) L10(-1.5,0.5) L11(-0.5,0.5) L12(0.5,0.5) L13(1.5,0.5) L14(2.5,0.5) L16(4.5,0.5) L17(5.5,0.5) L18(6.5,0.5) L19(7.5,0.5) L20(8.5,0.5) L21(9.5,0.5) L22(10.5,0.5) M1(-10.5,-0.5) M2(-9.5,-0.5) M3(-8.5,-0.5) M4(-7.5,-0.5) M5(-6.5,-0.5) M6(-5.5,-0.5) M7(-4.5,-0.5) M9(-2.5,-0.5) M10(-1.5,-0.5) M11(-0.5,-0.5) M12(0.5,-0.5) M13(1.5,-0.5) M14(2.5,-0.5) M16(4.5,-0.5) M17(5.5,-0.5) M18(6.5,-0.5) M19(7.5,-0.5) M20(8.5,-0.5) M21(9.5,-0.5) M22(10.5,-0.5) N1(-10.5,-1.5) N2(-9.5,-1.5) N3(-8.5,-1.5) N4(-7.5,-1.5) N5(-6.5,-1.5) N6(-5.5,-1.5) N7(-4.5,-1.5) N9(-2.5,-1.5) N10(-1.5,-1.5) N11(-0.5,-1.5) N12(0.5,-1.5) N13(1.5,-1.5) N14(2.5,-1.5) N16(4.5,-1.5) N17(5.5,-1.5) N18(6.5,-1.5) N19(7.5,-1.5) N20(8.5,-1.5) N21(9.5,-1.5) N22(10.5,-1.5) P1(-10.5,-2.5) P2(-9.5,-2.5) P3(-8.5,-2.5) P4(-7.5,-2.5) P5(-6.5,-2.5) P6(-5.5,-2.5) P7(-4.5,-2.5) P9(-2.5,-2.5) P10(-1.5,-2.5) P11(-0.5,-2.5) P12(0.5,-2.5) P13(1.5,-2.5) P14(2.5,-2.5) P16(4.5,-2.5) P17(5.5,-2.5) P18(6.5,-2.5) P19(7.5,-2.5) P20(8.5,-2.5) P21(9.5,-2.5) P22(10.5,-2.5) R1(-10.5,-3.5) R2(-9.5,-3.5) R3(-8.5,-3.5) R4(-7.5,-3.5) R5(-6.5,-3.5) R6(-5.5,-3.5) R7(-4.5,-3.5) R16(4.5,-3.5) R17(5.5,-3.5) R18(6.5,-3.5) R19(7.5,-3.5) R20(8.5,-3.5) R21(9.5,-3.5) R22(10.5,-3.5) T1(-10.5,-4.5) T2(-9.5,-4.5) T3(-8.5,-4.5) T4(-7.5,-4.5) T5(-6.5,-4.5) T6(-5.5,-4.5) T7(-4.5,-4.5) T8(-3.5,-4.5) T9(-2.5,-4.5) T10(-1.5,-4.5) T11(-0.5,-4.5) T12(0.5,-4.5) T13(1.5,-4.5) T14(2.5,-4.5) T15(3.5,-4.5) T16(4.5,-4.5) T17(5.5,-4.5) T18(6.5,-4.5) T19(7.5,-4.5) T20(8.5,-4.5) T21(9.5,-4.5) T22(10.5,-4.5) U1(-10.5,-5.5) U2(-9.5,-5.5) U3(-8.5,-5.5) U4(-7.5,-5.5) U5(-6.5,-5.5) U6(-5.5,-5.5) U7(-4.5,-5.5) U8(-3.5,-5.5) U9(-2.5,-5.5) U10(-1.5,-5.5) U11(-0.5,-5.5) U12(0.5,-5.5) U13(1.5,-5.5) U14(2.5,-5.5) U15(3.5,-5.5) U16(4.5,-5.5) U17(5.5,-5.5) U18(6.5,-5.5) U19(7.5,-5.5) U20(8.5,-5.5) U21(9.5,-5.5) U22(10.5,-5.5) V1(-10.5,-6.5) V2(-9.5,-6.5) V3(-8.5,-6.5) V4(-7.5,-6.5) V5(-6.5,-6.5) V6(-5.5,-6.5) V7(-4.5,-6.5) V8(-3.5,-6.5) V9(-2.5,-6.5) V10(-1.5,-6.5) V11(-0.5,-6.5) V12(0.5,-6.5) V13(1.5,-6.5) V14(2.5,-6.5) V15(3.5,-6.5) V16(4.5,-6.5) V17(5.5,-6.5) V18(6.5,-6.5) V19(7.5,-6.5) V20(8.5,-6.5) V21(9.5,-6.5) V22(10.5,-6.5) W1(-10.5,-7.5) W2(-9.5,-7.5) W3(-8.5,-7.5) W4(-7.5,-7.5) W5(-6.5,-7.5) W6(-5.5,-7.5) W7(-4.5,-7.5) W8(-3.5,-7.5) W9(-2.5,-7.5) W10(-1.5,-7.5) W11(-0.5,-7.5) W12(0.5,-7.5) W13(1.5,-7.5) W14(2.5,-7.5) W15(3.5,-7.5) W16(4.5,-7.5) W17(5.5,-7.5) W18(6.5,-7.5) W19(7.5,-7.5) W20(8.5,-7.5) W21(9.5,-7.5) W22(10.5,-7.5) Y1(-10.5,-8.5) Y2(-9.5,-8.5) Y3(-8.5,-8.5) Y4(-7.5,-8.5) Y5(-6.5,-8.5) Y6(-5.5,-8.5) Y7(-4.5,-8.5) Y8(-3.5,-8.5) Y9(-2.5,-8.5) Y10(-1.5,-8.5) Y11(-0.5,-8.5) Y12(0.5,-8.5) Y13(1.5,-8.5) Y14(2.5,-8.5) Y15(3.5,-8.5) Y16(4.5,-8.5) Y17(5.5,-8.5) Y18(6.5,-8.5) Y19(7.5,-8.5) Y20(8.5,-8.5) Y21(9.5,-8.5) Y22(10.5,-8.5)
  silkscreen extent -12.27,-11.5 11.5,11.5
HDR1X2H [mm]
  rect 1.5x1.5 hole 0.9: 1(0.012,-0.007)
  round 1.5 hole 0.9: 2(2.552,-0.007)
  silkscreen extent -1.26,-6.36 3.82,-1.28
MCCT-B [mm]
  rect 2x2.2 smd: 1(-1.5,0) 2(1.5,0)
  silkscreen extent -2.3,-1.6 1.8,1.6
MCCT-D [mm]
  rect 2.6x2.4 smd: 1(-3.2,0) 2(3.2,0)
  silkscreen extent -4.2,-2.4 3.7,2.4
QSOP16 [mm] "SSOP; 16 Leads; Body Width 3.9 mm; Pitch 0.635 mm"
  rect 0.4x2.2 smd: 1(-2.222,-2.6) 2(-1.587,-2.6) 3(-0.953,-2.6) 4(-0.318,-2.6) 5(0.318,-2.6) 6(0.953,-2.6) 7(1.587,-2.6) 8(2.222,-2.6) 9(2.222,2.6) 10(1.587,2.6) 11(0.953,2.6) 12(0.318,2.6) 13(-0.318,2.6) 14(-0.953,2.6) 15(-1.587,2.6) 16(-2.222,2.6)
  silkscreen extent -3.1,-2.72 2.5,1.1
"SMD _LED" [mm]
  rect 1.3x1.6 smd: 1(0.95,0) 2(-0.95,0)
  silkscreen extent -2.13,-1.15 2,1.15
SO-G5/P.95 [mm]
  rect 0.55x1.45 smd: 1(-0.959,-1.07) 2(-0.009,-1.07) 3(0.941,-1.07) 4(0.941,1.08) 5(-0.959,1.08)
  silkscreen extent -2.43,-2.19 1.64,2.21
SO-G44/P.8 [mm]
  rect 0.45x1.45 smd: 1(-8.4,-5.575) 2(-7.6,-5.575) 3(-6.8,-5.575) 4(-6,-5.575) 5(-5.2,-5.575) 6(-4.4,-5.575) 7(-3.6,-5.575) 8(-2.8,-5.575) 9(-2,-5.575) 10(-1.2,-5.575) 11(-0.4,-5.575) 12(0.4,-5.575) 13(1.2,-5.575) 14(2,-5.575) 15(2.8,-5.575) 16(3.6,-5.575) 17(4.4,-5.575) 18(5.2,-5.575) 19(6,-5.575) 20(6.8,-5.575) 21(7.6,-5.575) 22(8.4,-5.575) 23(8.4,5.575) 24(7.6,5.575) 25(6.8,5.575) 26(6,5.575) 27(5.2,5.575) 28(4.4,5.575) 29(3.6,5.575) 30(2.8,5.575) 31(2,5.575) 32(1.2,5.575) 33(0.4,5.575) 34(-0.4,5.575) 35(-1.2,5.575) 36(-2,5.575) 37(-2.8,5.575) 38(-3.6,5.575) 39(-4.4,5.575) 40(-5.2,5.575) 41(-6,5.575) 42(-6.8,5.575) 43(-7.6,5.575) 44(-8.4,5.575)
  silkscreen extent -9.3,-5.7 9.25,4.45
TestPin [mil] "SingleTest Pin"
  round 60 hole 35: 1(0,0)

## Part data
C1 C2 C3 C4 C5 C6 C7 C8 C9 C10 C11 C12 C13 C14 C15 C16 C53 C54 C55 C56 C57 C58: library part CAP_POLAR, "Polar Capacitor"
C17 C18 C19 C20 C21 C22 C23 C24 C25 C26 C27 C28 C29 C30 C31 C32 C33 C34 C35 C36 C37 C38 C39 C40 C41 C42 C43 C44 C45 C46 C47 C48 C49 C50 C51 C52 C59 C60 C61 C62: library part CAP, "Capacitor"
HDR1 HDR2: "Board-to-Board, Docking Station, 0.80mm (.031\") Pitch, Shielded Receptacle, Vertical, Ultra Low Profile, SMT"
JP1: "Header, 2-Pin, Right Angle"
LED1: library part HSMX-C670, "Typical RED GaAs SMD LED Agilent make"
LED2: library part HSMX-C670, "Typical GREEN GaAs SMD LED Agilent make"
R1 R2 R3 R4 R5 R6 R7 R8 R9 R10 R11 R12 R13: library part RES, "Resistor"
TP1 TP2 TP3 TP4 TP5 TP6 TP7 TP8 TP9 TP10 TP11 TP12 TP13 TP14 TP15: library part TestPin
U1: "Virtex-II 1.5V FPGA, 456-Ball FBGA, Commercial Grade"
U2: "SMBus Temperature Sensor with Internal and External Diode Input"
U3 U4: "512Kx16Bit SRAM TSOP44"
U5: library part SN74AHC1G04DBVR

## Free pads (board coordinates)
  round 1 smd far side mask+1.6: 0(19.8,21.8) 1(19.9,54.8) 1(59.1,6.3) 2(53,45.7)
  round 1 smd far side paste+1.5: 3(64.5,16.9)
  round 1 smd mask+3: 4(18.2,12.5) 5(17.5,64.4) 6(51.6,64.4) 7(53.2,12.6)
  round 3.2 hole 3.5 unplated: LP(4,34) LP(65,4) LP(65,73)

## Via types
v1: diameter 0.6, hole 0.3, Top Layer to Bottom Layer, tented bottom, 520 vias
v2: diameter 0.9, hole 0.5, Top Layer to Bottom Layer, 17 vias
v3: diameter 1.2, hole 0.7, Top Layer to Bottom Layer, 8 vias

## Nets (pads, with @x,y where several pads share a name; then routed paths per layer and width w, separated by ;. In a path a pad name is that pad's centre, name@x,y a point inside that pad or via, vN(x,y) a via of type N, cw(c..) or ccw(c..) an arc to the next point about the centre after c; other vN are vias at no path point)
5_V: HDR1.97 HDR1.99 TP5.1 | length 5.3
  Bottom Layer w0.3: HDR1.97@53.3,60.5 53.3,58.7 TP5.1@54,58 54.1,58.1 HDR1.99@54.1,60.5
5V: HDR2.97 HDR2.99 | length 3.7
  Bottom Layer w0.2: HDR2.97@53.3,9.7 53.3,8.3 53.4,8.2 54,8.2 54.1,8.3 HDR2.99@54.1,9.7
AUDIO_SPI_CSN: HDR1.11 U1.T4 | length 23.5
  MidLayer1 w0.127: 24.7,42.1 25.7,42.1
  MidLayer1 w0.2: v1(18.9,57.8) 18.9,55.7 20.1,54.5 20.1,46.2 24.2,42.1 24.7,42.1 ; 25.7,42.1 v1(26.2,41.6)
  Bottom Layer w0.2: v1(18.9,57.8) HDR1.11@18.9,60.5 ; v1(26.2,41.6) U1.T4@26.7,41.1
BLUE0: HDR1.14 U1.M3 | length 52.2
  MidLayer1 w0.2: v1(19.7,73.6) 19.7,66.231 13.3,59.831 13.3,56.4 16.9,52.8 16.9,43.9 24.2,36.6 v1(25.2,36.6)
  Bottom Layer w0.2: HDR1.14@19.7,67.3 v1(19.7,73.6) ; v1(25.2,36.6) U1.M3@25.7,37.1
BLUE1: HDR1.16 U1.N4 | length 51.6
  MidLayer1 w0.127: 24.7,37.1 25.7,37.1
  MidLayer1 w0.2: v1(20.5,73) 20.2,72.7 20.2,66.166 13.7,59.666 13.7,56.6 17.3,53 17.3,44.1 24.3,37.1 24.7,37.1 ; 25.7,37.1 v1(26.2,37.6)
  Bottom Layer w0.2: HDR1.16@20.5,67.3 v1(20.5,73) ; v1(26.2,37.6) U1.N4@26.7,38.1
BOC_CTS: HDR1.13 U1.U3 | length 21.4
  MidLayer1 w0.2: v1(19.7,58.9) 19.7,55.5 20.5,54.7 20.5,46.4 24.3,42.6 v1(25.2,42.6)
  Bottom Layer w0.2: v1(19.7,58.9) HDR1.13@19.7,60.5 ; v1(25.2,42.6) U1.U3@25.7,42.1
BOC_RTS: HDR1.17 U1.V3 | length 19.6
  MidLayer1 w0.2: v1(21.3,58.9) 21.3,46.9 24.6,43.6 v1(25.2,43.6)
  Bottom Layer w0.2: v1(21.3,58.9) HDR1.17@21.3,60.5 ; v1(25.2,43.6) U1.V3@25.7,43.1
BOC_RX: HDR1.19 U1.V4 | length 20.2
  MidLayer1 w0.2: v1(22.1,58.4) 22.1,56.366 21.9,56.166 21.9,50.3 21.7,50.1 21.7,47.1 24.5,44.3 25.5,44.3 v1(26.2,43.6)
  Bottom Layer w0.2: v1(22.1,58.4) HDR1.19@22.1,60.5 ; v1(26.2,43.6) U1.V4@26.7,43.1
BOC_TX: HDR1.15 U1.U4 | length 21.7
  MidLayer1 w0.127: 24.7,43.1 25.7,43.1
  MidLayer1 w0.2: v1(20.5,57.8) 20.5,55.4 20.9,55 20.9,46.6 24.4,43.1 24.7,43.1 ; 25.7,43.1 v1(26.2,42.6)
  Bottom Layer w0.2: v1(20.5,57.8) HDR1.15@20.5,60.5 ; v1(26.2,42.6) U1.U4@26.7,42.1
BUZZER: HDR2.24 U1.V20 | length 104.4
  MidLayer2 w0.2: v1(22.6,19.6) 22.9,19.3 22.9,10.366 21.1,8.566 21.1,6.9 21.5,6.5 22.634,6.5 23.034,6.1 25.5,6.1 25.9,5.7 27.9,5.7 28.8,6.6 35.734,6.6 36.434,5.9 38.2,5.9 38.3,5.8 39.9,5.8 40.7,5 41.8,5 42.4,5.6 49.634,5.6 51.134,4.1 55.7,4.1 57.1,5.5 57.1,8.2 54.2,11.1 54.2,17.1 54.8,17.7 54.8,18.2 53.5,19.5 53.5,23.9 52.3,25.1 52.3,31.934 53.5,33.134 53.5,35.1 51.4,37.2 51.2,37.4 51.2,40.2 48.8,42.6 v1(43.2,42.6)
  Bottom Layer w0.2: v1(22.6,19.6) 23.5,18.7 23.5,17.9 23.7,17.7 HDR2.24@23.7,16.5 ; U1.V20@42.7,43.1 v1(43.2,42.6)
CAN_RXD: HDR1.4 U1.K4 | length 50.3
  MidLayer1 w0.2: v1(15.7,68.9) 15.7,65.06 11.3,60.66 11.3,55.4 14.9,51.8 14.9,37.131 18.131,33.9 25.5,33.9 v1(26.2,34.6)
  Bottom Layer w0.2: HDR1.4@15.7,67.3 v1(15.7,68.9) ; v1(26.2,34.6) U1.K4@26.7,35.1
CAN_TXD: HDR1.2 U1.H4 | length 52.3
  MidLayer1 w0.2: v1(14.9,69.6) 14.9,64.825 10.9,60.825 10.9,55.1 14.5,51.5 14.5,36.966 18.266,33.2 25.6,33.2 26.142,32.658 v1(26.2,32.6)
  Bottom Layer w0.2: HDR1.2@14.9,67.3 v1(14.9,69.6) ; v1(26.2,32.6) U1.H4@26.7,33.1
DXN: C21.1 R10.2 U1.D5 U2.4 | length 36.1
  Top Layer w0.2: U2.4@3.682,19.4 3.682,21.282 v1(3.7,21.3)
  Top Layer w0.3: U2.4@3.682,19.4 3.682,17.518 3.85,17.35 C21.1@3.85,16.5 3.9,16.45 3.9,14.05 R10.2@3.95,14
  MidLayer1 w0.2: v1(25.5,24.5) 26.6,25.6 26.6,28 v1(27.2,28.6)
  Bottom Layer w0.2: v1(3.7,21.3) 4,21.6 10.266,21.6 12.866,24.2 24.766,24.2 25.066,24.5 v1(25.5,24.5) ; v1(27.2,28.6) U1.D5@27.7,29.1
DXP: C21.2 U1.A3 U2.3 | length 33
  Top Layer w0.2: U2.3@3.047,19.4 3.1,19.452 v1(3.1,22) 3.047,21.947 U2.3@3.047,19.4
  Top Layer w0.3: C21.2@2.15,16.5 2.15,17.15 3.047,18.048 U2.3@3.047,19.4
  Bottom Layer w0.2: v1(3.1,22) 10.1,22 12.7,24.6 24.6,24.6 25.7,25.7 U1.A3@25.7,26.1
FPGA_AUX0: HDR1.86 U1.B3 | length 118
  MidLayer1 w0.2: v1(5.2,38.1) 3.5,39.8 3.5,65.2 7.3,69 10.8,69 11.7,69.9 v1(11.7,72.2) ; v1(49,77.1) 49,75.9 49.6,75.3 v1(49.6,73)
  Bottom Layer w0.2: v1(5.2,38.1) 5.5,37.8 5.5,36.9 15.1,27.3 19.3,27.3 21.6,25 24.4,25 25.2,25.8 25.2,26.6 U1.B3@25.7,27.1 ; v1(11.7,72.2) 16.8,77.3 43.5,77.3 43.7,77.1 v1(49,77.1) ; HDR1.86@48.5,67.3 48.5,71.9 v1(49.6,73)
FPGA_AUX1: HDR1.88 U1.M19 | length 62.3
  MidLayer1 w0.127: 42.7,36.1 43.7,36.1
  MidLayer1 w0.2: v1(42.2,36.6) 42.7,36.1 ; 43.7,36.1 52.3,36.1 56.8,40.6 56.8,59.3 v1(56.4,59.7)
  Bottom Layer w0.2: U1.M19@41.7,37.1 v1(42.2,36.6) ; HDR1.88@49.3,67.3 49.3,71.6 50.2,72.5 56.9,72.5 57.4,72 57.4,67.3 56.4,66.3 v1(56.4,59.7)
FPGA_AUX2: HDR1.90 U1.M20 | length 59.1
  MidLayer1 w0.2: v1(43.2,36.6) 44.6,36.6 44.7,36.5 52,36.5 56.4,40.9 56.4,58.8 55.8,59.4 v1(55.8,60.7)
  Bottom Layer w0.2: U1.M20@42.7,37.1 v1(43.2,36.6) ; HDR1.90@50.1,67.3 50.1,68.5 50,68.6 50,71.6 50.5,72.1 56.7,72.1 57,71.8 57,67.6 55.8,66.4 v1(55.8,60.7)
FPGA_AUX3: HDR1.92 U1.N19 | length 57.7
  MidLayer1 w0.127: 42.7,37.1 43.7,37.1
  MidLayer1 w0.2: v1(42.2,37.6) 42.7,37.1 ; 43.7,37.1 44.4,37.1 45.6,38.3 53.1,38.3 55.2,40.4 v1(55.2,59.7)
  Bottom Layer w0.2: U1.N19@41.7,38.1 v1(42.2,37.6) ; HDR1.92@50.9,67.3 50.9,68.45 50.4,68.95 50.4,71.4 50.7,71.7 56.5,71.7 56.6,71.6 56.6,67.9 55.2,66.5 v1(55.2,59.7)
FPGA_CCLK: HDR1.66 R2.1 TP1.1 | length 10.5
  Top Layer w0.3: R2.1@38.05,71 38.05,72.35 39.2,73.5 TP1.1@40.5,73.5
  Bottom Layer w0.2: HDR1.66@40.5,67.3 TP1.1@40.5,73.5
FPGA_CLK: HDR2.2 TP9.1 U1.E12 | length 31.2
  MidLayer2 w0.127: 28.7,30.1 30.7,30.1
  MidLayer2 w0.2: TP9.1@13.5,16.5 15.3,16.5 22,23.2 22,27.2 24.2,29.4 26,29.4 26.7,30.1 26.8,30.2 28.6,30.2 28.7,30.1 ; 30.7,30.1 30.9,30.3 33.5,30.3 v1(34.2,29.6)
  Bottom Layer w0.2: TP9.1@13.5,16.5 HDR2.2@14.9,16.5 ; v1(34.2,29.6) U1.E12@34.7,30.1
FPGA_CLK_1: HDR1.30 U1.AB12 | length 37.1
  MidLayer1 w0.2: v1(26.1,69.9) 26.1,70.3 27.3,71.5 34.2,71.5 35.5,70.2 35.5,53.1 35.2,52.8 v1(35.2,52.4)
  Bottom Layer w0.2: HDR1.30@26.1,67.3 v1(26.1,69.9) ; U1.AB12@34.7,47.1 34.7,48.7 35.5,49.5 35.5,52 v1(35.2,52.4)
FPGA_CLK_2: HDR1.32 U1.V11 | length 41.2
  MidLayer1 w0.2: v1(26.9,68.9) 26.9,70.5 27.5,71.1 34,71.1 35.1,70 35.1,54.1 34.6,53.6 34.6,52 34.9,51.7 34.9,51.1 34.3,50.5 34.3,44.5 v1(35.2,43.6)
  Bottom Layer w0.2: HDR1.32@26.9,67.3 v1(26.9,68.9) ; U1.V11@33.7,43.1 34.2,43.6 v1(35.2,43.6)
FPGA_DIN: HDR1.64 U1.V18 | length 29.4
  MidLayer1 w0.2: v1(39.7,69.5) 39.7,63.2 40.7,62.2 40.7,56.1 40.2,55.6 v1(40.2,44.6)
  Bottom Layer w0.2: HDR1.64@39.7,67.3 v1(39.7,69.5) ; v1(40.2,44.6) 40.2,43.6 U1.V18@40.7,43.1
FPGA_DONE: HDR1.74 R7.1 U1.AB20 U5.2 | length 121.7
  Top Layer w0.3: R7.1@25.45,2 27,2 ; U5.2@25.57,5.991 26.709,5.991 27,5.7 27,2 ; v1(58.1,2.6) 56.6,1.1 28.5,1.1 27.6,2 27,2
  MidLayer1 w0.2: v1(43.7,69.1) 43.7,51.9 44.214,51.386 44.5,51.1 v1(44.5,49.7)
  MidLayer2 w0.2: v1(44.5,49.7) 45.7,48.5 51,48.5 55.981,43.519 55.981,33.319 56.5,32.8 56.5,28.403 55.9,27.803 55.9,20.666 57.6,18.966 57.6,14.772 57.4,14.572 57.4,11.6 59.5,9.5 59.5,4.334 58.5,3.334 58.5,3 v1(58.1,2.6)
  Bottom Layer w0.2: U1.AB20@42.7,47.1 42.7,47.5 43.3,48.1 43.8,48.1 44.5,48.8 v1(44.5,49.7) ; HDR1.74@43.7,67.3 v1(43.7,69.1)
FPGA_INIT: HDR1.68 R6.2 U1.AA19 | length 30.7
  Top Layer w0.3: v1(41.3,69) 43.2,70.9 43.2,72.2 42.7,72.7 R6.2@42.7,73.55
  MidLayer1 w0.2: v1(41.3,69) 41.3,64.6 42.2,63.7 v1(42.2,46.6)
  Bottom Layer w0.2: HDR1.68@41.3,67.3 v1(41.3,69) ; U1.AA19@41.7,46.1 v1(42.2,46.6)
FPGA_M0: HDR1.60 U1.AB2 | length 51.1
  MidLayer1 w0.2: v1(24.3,72.5) 22.8,72.5 21.4,71.1 21.4,68.769 26.8,63.369 26.8,58.5 26.5,58.2 v1(26.5,56.4)
  Bottom Layer w0.2: v1(24.3,72.5) 24.8,72 33.3,72 35,73.7 36.5,73.7 38.1,72.1 HDR1.60@38.1,67.3 ; U1.AB2@24.7,47.1 24.7,52.7 26.9,54.9 26.9,56 v1(26.5,56.4)
FPGA_M1: HDR1.58 U1.W3 | length 52.3
  MidLayer1 w0.2: v1(23.7,71.7) 22.7,71.7 21.8,70.8 21.8,68.934 27.2,63.534 v1(27.2,57.8)
  Bottom Layer w0.2: v1(23.7,71.7) 24.3,71.7 24.4,71.6 33.534,71.6 35.1,73.2 36.4,73.2 37.3,72.3 HDR1.58@37.3,67.3 HDR1.58@37.3,67.2 ; U1.W3@25.7,44.1 25.2,44.6 25.2,52.6 27.5,54.9 27.5,56.4 27.2,56.7 v1(27.2,57.8)
FPGA_M2: HDR1.56 U1.AB3 | length 47
  MidLayer1 w0.2: v1(23.1,71) 22.2,70.1 22.2,69.1 28,63.3 v1(28,57.1)
  Bottom Layer w0.2: v1(23.1,71) 33.5,71 35.3,72.8 36.234,72.8 36.5,72.534 HDR1.56@36.5,67.3 ; 25.697,52.303 25.703,52.303 28,54.6 v1(28,57.1) ; U1.AB3@25.7,47.1 25.7,52.2
FPGA_PROGRAM: HDR1.62 R5.1 TP2.1 U1.A2 | length 101.8
  Top Layer w0.2: TP2.1@27.3,74.4 29.45,74.4 R5.1@29.5,74.45
  MidLayer1 w0.2: v1(5.589,39.045) 5.589,56.08 12.7,63.191 v1(12.7,71.9) ; v1(39.3,72.4) 39.3,73.9 39.9,74.5 v1(39.9,75.5)
  Bottom Layer w0.2: v1(5.589,39.045) 5.9,38.734 5.9,37.1 15.3,27.7 19.5,27.7 21.8,25.4 24,25.4 U1.A2@24.7,26.1 ; v1(12.7,71.9) 15.2,74.4 TP2.1@27.3,74.4 30.6,74.4 32.3,76.1 39.3,76.1 v1(39.9,75.5) ; HDR1.62@38.9,67.3 38.9,72 v1(39.3,72.4)
FPGA_TCK: HDR1.72 TP6.1 U1.C19 | length 79.1
  Top Layer w0.2: v1(43.2,28.6) 56,28.6 56.7,27.9 v1(57.4,27.9)
  MidLayer1 w0.2: v1(43.1,69.8) 43.7,70.4 44.8,70.4 45.3,69.9 45.3,68.5 46.8,67 50.4,67 57.2,60.2 57.2,36.8 60.3,33.7 60.3,33.1 59.9,32.7 59.9,30.4 60.3,30 60.3,29.4 59.7,28.8 58.3,28.8 v1(57.4,27.9)
  Bottom Layer w0.2: U1.C19@41.7,28.1 42.2,28.6 v1(43.2,28.6) ; HDR1.72@42.9,67.3 42.9,69.6 v1(43.1,69.8) 43.1,72.1 TP6.1@45,74
FPGA_TDI: HDR1.78 TP3.1 U1.D3 | length 163.1
  MidLayer1 w0.2: v1(26.2,28.6) 26.2,27.5 24,25.3 24,19.2 21,16.2 21,4.7 22.534,3.166 22.6,3.1 54.9,3.1 58.8,7 61,7 64.2,10.2 64.2,16.8 63.5,17.5 63.5,32.5 63.1,32.9 63.1,40 65.8,42.7 65.8,54.8 64.9,55.7 v1(64.9,60.7)
  Bottom Layer w0.2: U1.D3@25.7,29.1 v1(26.2,28.6) ; HDR1.78@45.3,67.3 45.3,70.1 45,70.4 TP3.1@45,71.5 47.3,73.8 49.8,73.8 50.7,72.9 57.1,72.9 57.8,72.2 57.8,67.1 57,66.3 57,63.1 59.4,60.7 v1(64.9,60.7)
FPGA_TDO: HDR1.54 R3.1 TP4.1 | length 102.3
  Top Layer w0.2: R3.1@46.45,30 53.2,30 v1(53.7,30.5)
  MidLayer1 w0.2: v1(34.8,76.7) 34.8,73.1 v1(35.7,72.2) ; v1(48.4,76.4) 48.4,69.6 57.6,60.4 57.6,37.1 60.7,34 60.7,32.6 60.3,32.2 60.3,30.6 60.7,30.2 60.7,29.1 58.8,27.2 55.3,27.2 53.3,29.2 53.3,30.1 v1(53.7,30.5)
  Bottom Layer w0.2: v1(34.8,76.7) 39.9,76.7 40.7,75.9 43.6,75.9 44.1,76.4 v1(48.4,76.4) ; HDR1.54@35.7,67.3 v1(35.7,72.2)
  Bottom Layer w0.3: v1(48.4,76.4) 52.7,76.4 53.8,77.5 TP4.1@55.7,77.5
FPGA_TMS: HDR1.70 TP7.1 U1.B20 | length 96.4
  MidLayer1 w0.2: v1(49,74.6) 49,69.6 58,60.6 58,37.4 61.5,33.9 61.5,30.6 61.4,30.5 61.4,27 60,25.6 v1(60,20.1)
  Bottom Layer w0.2: HDR1.70@42.1,67.3 42.1,70.3 42,70.4 TP7.1@42,71.5 42,73.2 44.2,75.4 47.1,75.4 47.9,74.6 v1(49,74.6) ; U1.B20@42.7,27.1 43.2,26.6 43.2,25.8 48.6,20.4 52.069,20.4 53.869,18.6 58.5,18.6 v1(60,20.1)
